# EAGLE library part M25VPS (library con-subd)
SUB-D
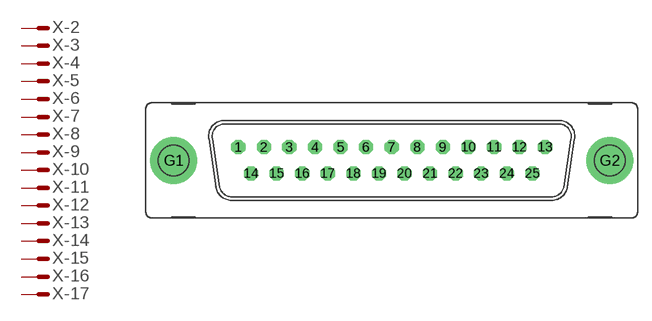
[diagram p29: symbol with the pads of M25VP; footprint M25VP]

Designator prefix X; gates -2=M -3=M -4=M -5=M -6=M -7=M -8=M -9=M -10=M -11=M -12=M -13=M -14=M -15=M -16=M -17=M -18=M -19=M -20=M -21=M -22=M -23=M -24=M -25=M -G=GND -1=MV

## M25VPS (OC_FARNELL: unknown; OC_NEWARK: unknown)  [M25VP]
1  -1:M  pas
2  -2:M  pas
3  -3:M  pas
4  -4:M  pas
5  -5:M  pas
6  -6:M  pas
7  -7:M  pas
8  -8:M  pas
9  -9:M  pas
10  -10:M  pas
11  -11:M  pas
12  -12:M  pas
13  -13:M  pas
14  -14:M  pas
15  -15:M  pas
16  -16:M  pas
17  -17:M  pas
18  -18:M  pas
19  -19:M  pas
20  -20:M  pas
21  -21:M  pas
22  -22:M  pas
23  -23:M  pas
24  -24:M  pas
25  -25:M  pas
G1  -G:G1  pas
G2  -G:G2  pas

## Footprint M25VP (pad centres in mm)
SUB-D
drill 1.016 octagon: 1 -16.561,1.422; 2 -13.792,1.422; 3 -11.049,1.422; 4 -8.28,1.422; 5 -5.512,1.422; 6 -2.769,1.422; 7 0,1.422; 8 2.769,1.422; 9 5.512,1.422; 10 8.28,1.422; 11 11.049,1.422; 12 13.792,1.422; 13 16.561,1.422; 14 -15.189,-1.422; 15 -12.421,-1.422; 16 -9.652,-1.422; 17 -6.909,-1.422; 18 -4.14,-1.422; 19 -1.372,-1.422; 20 1.372,-1.422; 21 4.14,-1.422; 22 6.909,-1.422; 23 9.652,-1.422; 24 12.421,-1.422; 25 15.189,-1.422
drill 3.302 pad 5.08 round: G1 -23.52,0; G2 23.52,0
